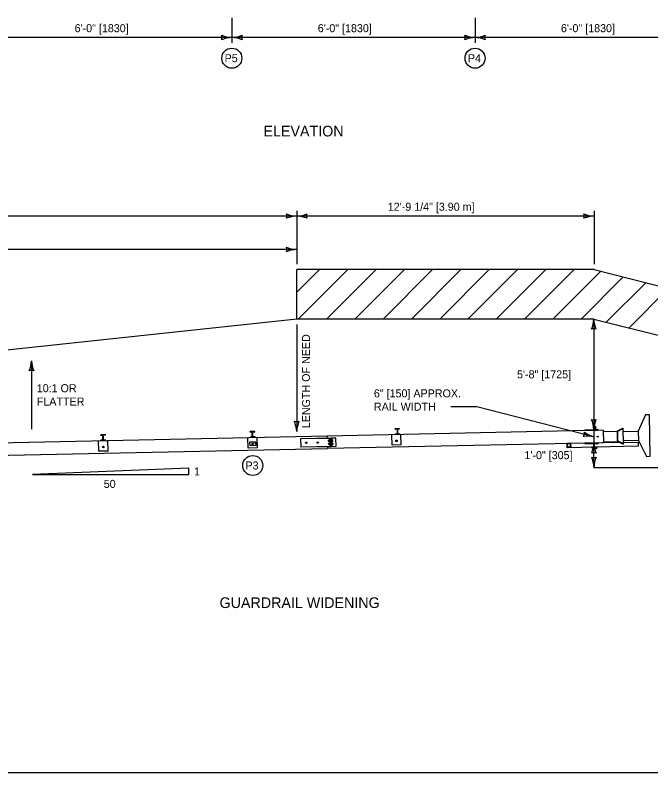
# Model space of a CAD drawing. Extents: x 49991.4 to 50021, y 49987.6 to 50011.4.
# Drawn here: x 50005.97 to 50010.73, y 49987.8 to 49993.48 of the extents above; entities that cross this region are included whole.
import ezdxf

# ---------------------------------------------------------------- set-up
doc = ezdxf.new("R2010")
doc.units = 0
for name, color, linetype in [('Level 1', 7, 'Continuous'), ('Level 2', 7, 'Continuous'), ('Level 3', 7, 'Continuous'), ('Level 4', 7, 'Continuous'), ('Level 63', 7, 'Continuous')]:
    doc.layers.add(name, color=color, linetype=linetype)

# ---------------------------------------------------------------- blocks, each defined once
blk = doc.blocks.new('HEX$NU')
at = {"layer": 'Level 63'}
for p, q in [((0, -0.32), (0, 0.32)), ((0.03, 0.43), (0.42, 0.43)), ((0.03, 0.22), (0.42, 0.22)), ((0.45, 0.32), (0.45, -0.32)), ((0.03, -0.22), (0.42, -0.22)), ((0.42, -0.43), (0.03, -0.43))]:
    blk.add_line(p, q, dxfattribs=at)
for centre, radius, start, end in [((0.21, 0.32), 0.21, 149.0201, 210.9799), ((0.8, 0), 0.796, 164.2217, 195.7782), ((0.24, 0.32), 0.21, 329.0201, 30.9799), ((-0.35, 0), 0.796, 344.2218, 15.7783), ((0.21, -0.32), 0.21, 149.0201, 210.9799), ((0.24, -0.32), 0.21, 329.0201, 30.9799)]:
    blk.add_arc(centre, radius, start, end, dxfattribs=at)

msp = doc.modelspace()

# ---------------------------------------------------------------- linework, layer by layer
at = {"layer": 'Level 1'}
for p, q in [((50008.0791, 49991.2004), (50008.0791, 49991.5719)), ((50008.0791, 49991.4009), (50008.2501, 49991.5719)), ((50010.3087, 49991.5719), (50008.0791, 49991.5719)), ((50008.0908, 49991.2004), (50008.4623, 49991.5719)), ((50008.3029, 49991.2004), (50008.6744, 49991.5719)), ((50008.5149, 49991.2004), (50008.8864, 49991.5719)), ((50008.7271, 49991.2004), (50009.0986, 49991.5719)), ((50008.9393, 49991.2004), (50009.3108, 49991.5719)), ((50009.1513, 49991.2004), (50009.5228, 49991.5719)), ((50009.3635, 49991.2004), (50009.735, 49991.5719)), ((50009.5757, 49991.2004), (50009.9472, 49991.5719)), ((50009.7877, 49991.2004), (50010.1592, 49991.5719)), ((50009.9999, 49991.2004), (50010.3586, 49991.5591)), ((50010.3087, 49991.5719), (50016.0878, 49990.0886)), ((50010.212, 49991.2004), (50010.5274, 49991.5157)), ((50010.4006, 49991.1767), (50010.6963, 49991.4724)), ((50010.5708, 49991.1348), (50010.8651, 49991.4291)), ((50008.0791, 49991.2004), (50001.0367, 49990.4473)), ((50010.3072, 49991.2004), (50008.0791, 49991.2004)), ((50010.3072, 49991.2004), (50014.7014, 49990.0886)), ((50010.6948, 49990.4815), (50010.6398, 49990.3599)), ((50010.7235, 49990.4821), (50010.6948, 49990.4815)), ((50010.73, 49990.1715), (50010.7235, 49990.4821)), ((50010.3783, 49990.3661), (50008.3088, 49990.3226)), ((50008.8174, 49990.3799), (50008.8509, 49990.3806)), ((50008.8175, 49990.3758), (50008.8174, 49990.3799)), ((50008.8175, 49990.3758), (50008.8294, 49990.3761)), ((50008.8331, 49990.3723), (50008.8338, 49990.3415)), ((50008.8356, 49990.3723), (50008.8362, 49990.3416)), ((50008.8391, 49990.3763), (50008.851, 49990.3765)), ((50008.851, 49990.3765), (50008.8509, 49990.3806)), ((50010.2413, 49990.3638), (50010.2413, 49990.3632)), ((50010.2478, 49990.3633), (50010.2478, 49990.364)), ((50010.3097, 49990.3792), (50010.3098, 49990.3736)), ((50010.3098, 49990.3736), (50010.3098, 49990.3717)), ((50010.3131, 49990.3799), (50010.3116, 49990.3798)), ((50010.3118, 49990.3711), (50010.3234, 49990.3714)), ((50010.3126, 49990.3928), (50010.3135, 49990.3938)), ((50010.3126, 49990.3928), (50010.3135, 49990.3938)), ((50010.3126, 49990.3928), (50010.3129, 49990.3798)), ((50010.3131, 49990.3799), (50010.3233, 49990.3801)), ((50010.3207, 49990.394), (50010.3135, 49990.3938)), ((50010.3207, 49990.394), (50010.3135, 49990.3938)), ((50010.3137, 49990.3717), (50010.3135, 49990.3793)), ((50010.3216, 49990.393), (50010.3207, 49990.394)), ((50010.3216, 49990.393), (50010.3207, 49990.394)), ((50010.3215, 49990.3719), (50010.3213, 49990.3794)), ((50010.3219, 49990.38), (50010.3216, 49990.393)), ((50010.3253, 49990.3744), (50010.3252, 49990.3795)), ((50010.3253, 49990.3744), (50010.3254, 49990.372)), ((50010.3281, 49990.3715), (50010.3328, 49990.3716)), ((50010.3329, 49990.3657), (50010.3282, 49990.3656)), ((50010.3329, 49990.3657), (50010.333, 49990.3651)), ((50010.3783, 49990.3661), (50010.3802, 49990.2729)), ((50010.4841, 49990.3619), (50010.5237, 49990.3829)), ((50010.5238, 49990.3776), (50010.4842, 49990.3567)), ((50010.5237, 49990.3829), (50010.5261, 49990.3777)), ((50010.5261, 49990.3777), (50010.5238, 49990.3776)), ((50010.5238, 49990.3776), (50010.5261, 49990.2675)), ((50010.5272, 49990.3226), (50010.5261, 49990.3777)), ((50010.5272, 49990.3226), (50010.5261, 49990.3741)), ((50008.3088, 49990.3226), (50004.9581, 49990.2521)), ((50006.6462, 49990.3342), (50006.61, 49990.3335)), ((50006.6102, 49990.3279), (50006.61, 49990.3335)), ((50006.6255, 49990.3282), (50006.6102, 49990.3279)), ((50006.6263, 49990.2928), (50006.6255, 49990.3282)), ((50006.6464, 49990.3286), (50006.6311, 49990.3283)), ((50006.6319, 49990.2929), (50006.6311, 49990.3283)), ((50006.6464, 49990.3286), (50006.6462, 49990.3342)), ((50007.766, 49990.3578), (50007.7298, 49990.357)), ((50007.7299, 49990.3514), (50007.7298, 49990.357)), ((50007.7452, 49990.3518), (50007.7299, 49990.3514)), ((50007.746, 49990.3164), (50007.7307, 49990.316)), ((50007.7308, 49990.3104), (50007.7307, 49990.316)), ((50007.746, 49990.3164), (50007.7452, 49990.3518)), ((50007.7661, 49990.3522), (50007.7508, 49990.3519)), ((50007.7516, 49990.3164), (50007.7508, 49990.3519)), ((50007.7669, 49990.3168), (50007.7516, 49990.3164)), ((50007.7661, 49990.3522), (50007.766, 49990.3578)), ((50007.7669, 49990.3112), (50007.7669, 49990.3168)), ((50008.3379, 49990.3076), (50008.1079, 49990.3028)), ((50008.2364, 49990.3055), (50008.3307, 49990.3075)), ((50008.3091, 49990.307), (50008.3088, 49990.3226)), ((50008.3088, 49990.3226), (50008.3091, 49990.307)), ((50008.332, 49990.2454), (50008.3307, 49990.3075)), ((50008.3738, 49990.3084), (50008.3379, 49990.3076)), ((50008.3392, 49990.2455), (50008.3379, 49990.3076)), ((50008.3428, 49990.2456), (50008.3415, 49990.3077)), ((50008.3751, 49990.2463), (50008.3738, 49990.3084)), ((50008.8585, 49990.3341), (50008.7938, 49990.3328)), ((50008.8302, 49990.3376), (50008.8183, 49990.3373)), ((50008.8184, 49990.3333), (50008.8183, 49990.3373)), ((50008.8519, 49990.334), (50008.8184, 49990.3333)), ((50008.8518, 49990.338), (50008.8399, 49990.3378)), ((50008.8519, 49990.334), (50008.8518, 49990.338)), ((50010.3784, 49990.3583), (50010.4842, 49990.3605)), ((50010.4861, 49990.3576), (50010.4841, 49990.3619)), ((50010.4842, 49990.3605), (50010.4848, 49990.3295)), ((50010.4842, 49990.3567), (50010.4857, 49990.2868)), ((50010.4857, 49990.2868), (50010.4842, 49990.3567)), ((50010.4842, 49990.3567), (50010.4865, 49990.3567)), ((50010.4858, 49990.2829), (50010.4851, 49990.314)), ((50010.4861, 49990.3576), (50010.4865, 49990.3567)), ((50010.5265, 49990.3576), (50010.6398, 49990.3599)), ((50010.5272, 49990.3226), (50010.5284, 49990.2675)), ((50010.5272, 49990.3226), (50010.5283, 49990.2712)), ((50010.6398, 49990.3599), (50010.6413, 49990.2901)), ((50006.6263, 49990.2928), (50006.611, 49990.2925)), ((50006.611, 49990.2869), (50006.611, 49990.2925)), ((50006.6472, 49990.2932), (50006.6319, 49990.2929)), ((50006.6472, 49990.2876), (50006.6472, 49990.2932)), ((50007.773, 49990.2784), (50007.7264, 49990.2774)), ((50007.7264, 49990.2774), (50007.727, 49990.2501)), ((50007.7735, 49990.2512), (50007.727, 49990.2501)), ((50007.7691, 49990.2784), (50007.7696, 49990.2511)), ((50007.773, 49990.2784), (50007.7735, 49990.2512)), ((50008.1079, 49990.3028), (50008.1092, 49990.2407)), ((50010.3802, 49990.2729), (50008.3108, 49990.2294)), ((50008.3193, 49990.2927), (50008.3184, 49990.2917)), ((50008.3186, 49990.2839), (50008.3184, 49990.2917)), ((50008.3195, 49990.283), (50008.3186, 49990.2839)), ((50008.3198, 49990.2694), (50008.3189, 49990.2684)), ((50008.3191, 49990.2606), (50008.3189, 49990.2684)), ((50008.32, 49990.2597), (50008.3191, 49990.2606)), ((50008.3193, 49990.2927), (50008.3231, 49990.2928)), ((50008.3193, 49990.2927), (50008.3195, 49990.283)), ((50008.3231, 49990.2918), (50008.3193, 49990.2917)), ((50008.3195, 49990.284), (50008.3233, 49990.284)), ((50008.3233, 49990.2831), (50008.3195, 49990.283)), ((50008.3198, 49990.2694), (50008.3236, 49990.2695)), ((50008.3198, 49990.2694), (50008.32, 49990.2597)), ((50008.3236, 49990.2685), (50008.3198, 49990.2684)), ((50008.32, 49990.2607), (50008.3238, 49990.2607)), ((50008.3238, 49990.2598), (50008.32, 49990.2597)), ((50008.3477, 49990.2926), (50008.3418, 49990.2925)), ((50008.3479, 49990.2842), (50008.342, 49990.2841)), ((50008.3482, 49990.2693), (50008.3423, 49990.2692)), ((50008.3484, 49990.2609), (50008.3424, 49990.2608)), ((50008.3483, 49990.2947), (50008.3485, 49990.2821)), ((50008.3488, 49990.2715), (50008.349, 49990.2589)), ((50010.4986, 49990.2754), (50010.1072, 49990.2672)), ((50010.1078, 49990.2361), (50010.1072, 49990.2672)), ((50010.1113, 49990.242), (50010.1109, 49990.2614)), ((50010.1306, 49990.2638), (50010.1126, 49990.2634)), ((50010.1328, 49990.2425), (50010.1324, 49990.2619)), ((50010.1366, 49990.2367), (50010.1359, 49990.2678)), ((50010.2498, 49990.2702), (50010.2498, 49990.2695)), ((50010.3284, 49990.2718), (50010.3284, 49990.2712)), ((50010.3349, 49990.272), (50010.3349, 49990.2713)), ((50010.3801, 49990.2807), (50010.4858, 49990.2829)), ((50010.5261, 49990.2675), (50010.4857, 49990.2868)), ((50010.4876, 49990.2859), (50010.4858, 49990.2815)), ((50010.4858, 49990.2815), (50010.5262, 49990.2622)), ((50010.5284, 49990.2675), (50010.5261, 49990.2675)), ((50010.5262, 49990.2622), (50010.5284, 49990.2675)), ((50010.6413, 49990.2901), (50010.528, 49990.2877)), ((50010.5282, 49990.276), (50010.6389, 49990.2784)), ((50010.6389, 49990.2784), (50010.6396, 49990.2473)), ((50010.6413, 49990.2901), (50010.7013, 49990.1709)), ((50008.3392, 49990.2455), (50008.1092, 49990.2407)), ((50008.2377, 49990.2434), (50008.332, 49990.2454)), ((50008.3104, 49990.2449), (50008.3108, 49990.2294)), ((50008.3392, 49990.2455), (50008.3751, 49990.2463)), ((50010.6396, 49990.2473), (50010.1078, 49990.2361)), ((50010.1311, 49990.2405), (50010.1131, 49990.2401)), ((50010.2899, 49990.2371), (50010.2946, 49990.2372)), ((50010.2899, 49990.2371), (50010.2946, 49990.2372)), ((50010.2907, 49990.2374), (50010.2906, 49990.24)), ((50010.2907, 49990.2374), (50010.2906, 49990.24)), ((50010.2938, 49990.2375), (50010.2938, 49990.24)), ((50010.2938, 49990.2375), (50010.2938, 49990.24)), ((50010.3146, 49990.232), (50010.3286, 49990.2323)), ((50010.3146, 49990.232), (50010.3286, 49990.2323)), ((50010.3169, 49990.2328), (50010.3168, 49990.2405)), ((50010.3169, 49990.2328), (50010.3168, 49990.2405)), ((50010.3263, 49990.233), (50010.3261, 49990.2407)), ((50010.3263, 49990.233), (50010.3261, 49990.2407)), ((50010.7013, 49990.1709), (50010.73, 49990.1715))]:
    msp.add_line(p, q, dxfattribs=at)
for points in [[(49999.3835, 49998.9992), (50016.7501, 49998.9992), (50016.7501, 49987.7988), (49999.3835, 49987.7988)], [(50010.336, 49990.3228), (50010.3394, 49990.3208), (50010.3395, 49990.3166), (50010.3362, 49990.3144), (50010.3328, 49990.3164), (50010.3327, 49990.3206)]]:
    msp.add_lwpolyline(points, close=True, dxfattribs=at)
for points in [[(50010.3329, 49990.3657), (50010.2413, 49990.3638), (50010.2411, 49990.3696), (50010.3328, 49990.3716)], [(50008.348, 49990.28), (50008.342, 49990.2799), (50008.3417, 49990.2967), (50008.3476, 49990.2968)], [(50008.3484, 49990.2567), (50008.3425, 49990.2566), (50008.3422, 49990.2734), (50008.3481, 49990.2735)], [(50010.3351, 49990.2655), (50010.2434, 49990.2636), (50010.2432, 49990.2694), (50010.3349, 49990.2713)], [(50004.9601, 49990.1589), (50008.3108, 49990.2294)], [(50010.2954, 49990.2375), (50010.2953, 49990.2401), (50010.2891, 49990.2399), (50010.2891, 49990.2374)], [(50010.2954, 49990.2375), (50010.2953, 49990.2401), (50010.2891, 49990.2399), (50010.2891, 49990.2374)], [(50010.3309, 49990.2331), (50010.3308, 49990.2408), (50010.3121, 49990.2404), (50010.3123, 49990.2327)], [(50010.3309, 49990.2331), (50010.3308, 49990.2408), (50010.3121, 49990.2404), (50010.3123, 49990.2327)], [(50010.308, 49990.0886), (50016.0878, 49990.0886)]]:
    msp.add_lwpolyline(points, dxfattribs=at)
for centre in [(50007.7499, 49990.2642), (50008.8275, 49990.2874), (50006.6302, 49990.2407)]:
    msp.add_circle(centre, 0.00582, dxfattribs=at)
for centre, major_axis, start_param, end_param in [((50008.8295, 49990.3722), (0.00008, -0.00388), 1.570796, 3.141593), ((50008.8391, 49990.3724), (0.00008, -0.00388), 3.141593, 4.712389), ((50010.3117, 49990.3757), (0.00009, -0.00408), 2.720968, 3.682294), ((50010.3117, 49990.3752), (0.00009, -0.00408), 5.742484, 6.823887), ((50010.3117, 49990.3757), (0.00009, -0.00408), 2.600891, 2.720968), ((50010.3177, 49990.3645), (0.0003, -0.0155), 2.86621, 3.416974), ((50010.3173, 49990.3867), (0.0003, -0.0155), 6.007804, 6.558569), ((50010.3233, 49990.376), (0.00009, -0.00408), 2.967765, 3.682294), ((50010.3234, 49990.3755), (0.00009, -0.00408), 5.742484, 6.823887), ((50010.3233, 49990.376), (0.00009, -0.00408), 2.600891, 2.967765), ((50010.3331, 49990.3599), (0.0002, -0.0116), 2.033833, 3.141593), ((50010.3331, 49990.3599), (0.00012, -0.00582), 2.675505, 3.141593), ((50008.8302, 49990.3415), (0.00008, -0.00388), 0, 1.570796), ((50008.8398, 49990.3417), (0.00008, -0.00388), 4.712389, 6.283185), ((50010.3361, 49990.3186), (0.00005, -0.00216), 4.763342, 5.105427), ((50010.3361, 49990.3186), (0.00005, -0.00216), 4.763342, 5.105427), ((50010.3361, 49990.3186), (0.00005, -0.00216), 3.992248, 4.383081), ((50010.3361, 49990.3186), (0.00005, -0.00216), 3.992248, 4.383081), ((50010.3361, 49990.3186), (0.00005, -0.00216), 5.354777, 5.790079), ((50010.3361, 49990.3186), (0.00005, -0.00216), 5.354777, 5.790079), ((50010.3361, 49990.3186), (0.00005, -0.00216), 3.449353, 3.624539), ((50010.3361, 49990.3186), (0.00005, -0.00216), 3.449353, 3.624539), ((50010.3361, 49990.3186), (0.00005, -0.00216), 2.884373, 3.117684), ((50010.3361, 49990.3186), (0.00005, -0.00216), 2.884373, 3.117684), ((50010.3361, 49990.3186), (0.00005, -0.00216), 2.884373, 3.117684), ((50010.3361, 49990.3186), (0.00005, -0.00216), 2.884373, 3.117684), ((50010.3361, 49990.3186), (0.00005, -0.00216), 6.236416, 6.677165), ((50010.3361, 49990.3186), (0.00005, -0.00216), 2.117521, 2.495297), ((50010.3361, 49990.3186), (0.00005, -0.00216), 2.117521, 2.495297), ((50010.3361, 49990.3186), (0.00005, -0.00216), 2.117521, 2.495297), ((50010.3361, 49990.3186), (0.00005, -0.00216), 2.117521, 2.495297), ((50010.3361, 49990.3186), (0.00005, -0.00216), 0.757801, 1.088721), ((50010.3361, 49990.3186), (0.00005, -0.00216), 0.757801, 1.088721), ((50010.3361, 49990.3186), (0.00005, -0.00216), 0.757801, 1.088721), ((50010.3361, 49990.3186), (0.00005, -0.00216), 0.757801, 1.088721), ((50010.3361, 49990.3186), (0.00005, -0.00216), 1.432819, 1.796691), ((50010.3361, 49990.3186), (0.00005, -0.00216), 1.432819, 1.796691), ((50010.3361, 49990.3186), (0.00005, -0.00216), 1.432819, 1.796691), ((50010.3361, 49990.3186), (0.00005, -0.00216), 1.432819, 1.796691), ((50008.3449, 49990.2947), (0.00008, -0.00359), 0.945365, 2.196228), ((50008.3361, 49990.2882), (0.0003, -0.0133), 1.250246, 1.891347), ((50008.3452, 49990.2821), (0.00008, -0.00359), 0.945366, 2.196226), ((50008.3454, 49990.2714), (0.00008, -0.00359), 0.945365, 2.196228), ((50008.3365, 49990.2649), (0.0003, -0.0133), 1.250246, 1.891347), ((50008.3457, 49990.2588), (0.00008, -0.00359), 0.945366, 2.196226), ((50010.1127, 49990.2615), (0.00004, -0.00194), 3.141593, 4.712389), ((50010.1306, 49990.2618), (0.00004, -0.00194), 1.570796, 3.141593), ((50010.3348, 49990.2772), (0.00012, -0.00582), 0, 0.466088), ((50010.3348, 49990.2772), (0.0002, -0.0116), 0, 1.10776), ((50010.1131, 49990.2421), (0.00004, -0.00194), 4.712389, 6.283185), ((50010.131, 49990.2424), (0.00004, -0.00194), 0, 1.570796), ((50010.2899, 49990.2386), (0.00003, -0.00144), 5.657754, 6.908617), ((50010.2899, 49990.2386), (0.00003, -0.00144), 5.657754, 6.908617), ((50010.2922, 49990.2425), (0.00011, -0.00533), 5.962635, 6.603736), ((50010.2922, 49990.2425), (0.00011, -0.00533), 5.962635, 6.603736), ((50010.2946, 49990.2387), (0.00003, -0.00144), 5.657755, 6.908615), ((50010.2946, 49990.2387), (0.00003, -0.00144), 5.657755, 6.908615), ((50010.3145, 49990.2363), (0.00009, -0.00431), 5.657754, 6.908617), ((50010.3145, 49990.2363), (0.00009, -0.00431), 5.657754, 6.908617), ((50010.3213, 49990.2481), (0.0003, -0.016), 5.962635, 6.603736), ((50010.3213, 49990.2481), (0.0003, -0.016), 5.962635, 6.603736), ((50010.3285, 49990.2366), (0.00009, -0.00431), 5.657755, 6.908615), ((50010.3285, 49990.2366), (0.00009, -0.00431), 5.657755, 6.908615)]:
    msp.add_ellipse(centre, major_axis=major_axis, ratio=0.925528, start_param=start_param, end_param=end_param, dxfattribs=at)
for centre, major_axis in [((50010.3361, 49990.3186), (0.00005, -0.00243)), ((50010.3361, 49990.3186), (0.00005, -0.00243)), ((50008.1511, 49990.2726), (0.00012, -0.00566)), ((50008.2373, 49990.2745), (0.00012, -0.00566))]:
    msp.add_ellipse(centre, major_axis=major_axis, ratio=0.925528, dxfattribs=at)
at = {"layer": 'Level 2'}
for p, q in [((50007.2698, 49990.0814), (50006.0979, 49990.0346)), ((50007.2698, 49990.0346), (50007.2698, 49990.0814)), ((50006.0979, 49990.0346), (50007.2698, 49990.0346))]:
    msp.add_line(p, q, dxfattribs=at)
for centre in [(50007.5932, 49993.1553), (50009.4164, 49993.1553), (50007.7499, 49990.1026)]:
    msp.add_circle(centre, 0.075, dxfattribs=at)
at = {"layer": 'Level 3'}
for p, q in [((50007.5932, 49993.458), (50007.5932, 49993.2703)), ((50009.4164, 49993.458), (50009.4164, 49993.2703)), ((50007.5932, 49993.3103), (50005.7702, 49993.3103)), ((50009.4164, 49993.3103), (50007.5932, 49993.3103)), ((50011.2396, 49993.3103), (50009.4164, 49993.3103)), ((50008.0791, 49992.0119), (50008.0791, 49991.6119)), ((50010.3086, 49992.0119), (50010.3086, 49991.6119)), ((50008.0791, 49991.9719), (50001.0367, 49991.9719)), ((50010.3086, 49991.9719), (50008.0791, 49991.9719)), ((50008.0791, 49991.7219), (50001.5952, 49991.7219)), ((50008.0791, 49991.1604), (50008.0791, 49990.3577)), ((50010.3063, 49991.2004), (50010.3063, 49990.371)), ((50006.0906, 49990.8877), (50006.0906, 49990.3759)), ((50009.4309, 49990.5432), (50009.2355, 49990.5432)), ((50010.3072, 49990.3176), (50009.4309, 49990.5432)), ((50010.3063, 49990.3646), (50010.308, 49990.2714)), ((50010.308, 49990.0886), (50010.308, 49990.2714))]:
    msp.add_line(p, q, dxfattribs=at)
for centre, radius, start, end in [((50007.6024, 49993.5324), 0.2223, 247.456, 267.6395), ((50007.465, 49993.3103), 0.0548, 342.1388, 17.8612), ((50007.5817, 49993.543), 0.233, 272.8273, 292.0772), ((50007.7214, 49993.3103), 0.0548, 162.1388, 197.8612), ((50009.4256, 49993.5324), 0.2223, 247.456, 267.6395), ((50009.2882, 49993.3103), 0.0548, 342.1388, 17.8612), ((50009.4049, 49993.543), 0.233, 272.8273, 292.0772), ((50009.5446, 49993.3103), 0.0548, 162.1388, 197.8612), ((50007.6047, 49993.0776), 0.233, 92.8273, 112.0772), ((50007.584, 49993.0882), 0.2223, 67.456, 87.6395), ((50009.4279, 49993.0776), 0.233, 92.8273, 112.0772), ((50009.4072, 49993.0882), 0.2223, 67.456, 87.6395), ((50008.0883, 49992.194), 0.2223, 247.456, 267.6395), ((50007.9509, 49991.9719), 0.0548, 342.1388, 17.8612), ((50008.0906, 49991.7392), 0.233, 92.8273, 112.0772), ((50008.0676, 49992.2046), 0.233, 272.8273, 292.0772), ((50008.0699, 49991.7498), 0.2223, 67.456, 87.6395), ((50008.2073, 49991.9719), 0.0548, 162.1388, 197.8612), ((50010.3178, 49992.194), 0.2223, 247.456, 267.6395), ((50010.1804, 49991.9719), 0.0548, 342.1388, 17.8612), ((50010.3201, 49991.7392), 0.233, 92.8273, 112.0772), ((50008.0883, 49991.944), 0.2223, 247.456, 267.6395), ((50007.9509, 49991.7219), 0.0548, 342.1388, 17.8612), ((50008.0906, 49991.4892), 0.233, 92.8273, 112.0772), ((50010.0842, 49991.2095), 0.2223, 337.456, 357.6395), ((50010.539, 49991.2119), 0.233, 182.8273, 202.0772), ((50010.3063, 49991.0722), 0.0548, 72.1388, 107.8612), ((50005.8685, 49990.8969), 0.2223, 337.456, 357.6395), ((50006.3233, 49990.8992), 0.233, 182.8273, 202.0772), ((50006.0906, 49990.7595), 0.0548, 72.1388, 107.8612), ((50008.0791, 49990.4859), 0.0548, 252.1388, 287.8612), ((50007.8464, 49990.3462), 0.233, 2.8273, 22.0772), ((50008.3012, 49990.3486), 0.2223, 157.456, 177.6395), ((50010.3063, 49990.4992), 0.0548, 252.1388, 287.8612), ((50010.0736, 49990.3595), 0.233, 2.8273, 22.0772), ((50010.5284, 49990.3619), 0.2223, 157.456, 177.6395), ((50010.1826, 49990.3479), 0.0548, 328.4642, 4.1866), ((50010.2633, 49990.0887), 0.233, 79.1527, 98.4026), ((50010.3686, 49990.5312), 0.2223, 233.7814, 253.9649), ((50010.0859, 49990.2806), 0.2223, 337.456, 357.6395), ((50010.5407, 49990.2829), 0.233, 182.8273, 202.0772), ((50010.308, 49990.1432), 0.0548, 72.1388, 107.8612), ((50010.308, 49990.2168), 0.0548, 252.1388, 287.8612), ((50010.0753, 49990.0771), 0.233, 2.8273, 22.0772), ((50010.5301, 49990.0794), 0.2223, 157.456, 177.6395)]:
    msp.add_arc(centre, radius, start, end, dxfattribs=at)
at = {"layer": 'Level 4'}
for p, q in [((50007.7155, 49990.2324), (50007.7139, 49990.3101)), ((50007.7854, 49990.2338), (50007.7837, 49990.3115)), ((50008.7955, 49990.2551), (50008.7938, 49990.3328)), ((50008.8585, 49990.3341), (50008.8601, 49990.2565)), ((50006.5958, 49990.2088), (50006.5941, 49990.2866)), ((50006.6656, 49990.2104), (50006.664, 49990.288)), ((50008.8601, 49990.2565), (50008.7955, 49990.2551)), ((50006.6656, 49990.2104), (50006.5958, 49990.2088)), ((50007.7854, 49990.2338), (50007.7155, 49990.2324))]:
    msp.add_line(p, q, dxfattribs=at)

# ---------------------------------------------------------------- block references
at = {"layer": 'Level 1', "xscale": 0.017968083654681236, "yscale": -0.019413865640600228, "rotation": 1.2045520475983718}
for p in [(50008.3232, 49990.2886), (50008.3238, 49990.2652)]:
    msp.add_blockref('HEX$NU', p, dxfattribs=at)

# ---------------------------------------------------------------- texts
at = {"layer": 'Level 2'}
for s, height, p in [('6\'-0" [1830]', 0.06, (50006.4142, 49993.3503)), ('6\'-0" [1830]', 0.06, (50008.2373, 49993.3503)), ('6\'-0" [1830]', 0.06, (50010.0605, 49993.3503)), ('P5', 0.06, (50007.5389, 49993.1253)), ('P4', 0.06, (50009.363, 49993.1253)), ('ELEVATION', 0.08, (50007.8304, 49992.5689)), ('12\'-9 1/4" [3.90 m]', 0.06, (50008.7622, 49992.0119)), ('5\'-8" [1725]', 0.06, (50009.7312, 49990.7557)), ('10:1 OR', 0.06, (50006.1306, 49990.6518)), ('6" [150] APPROX. ', 0.06, (50008.6582, 49990.6132)), ('FLATTER', 0.06, (50006.1306, 49990.5518)), ('RAIL WIDTH', 0.06, (50008.6582, 49990.5132)), ('1\'-0" [305]', 0.06, (50009.7868, 49990.15)), ('1', 0.06, (50007.3098, 49990.028)), ('P3', 0.06, (50007.6953, 49990.0726)), ('50', 0.06, (50006.6327, 49989.9346)), ('GUARDRAIL WIDENING', 0.08, (50007.5011, 49989.0342))]:
    msp.add_text(s, height=height, dxfattribs=at).set_placement(p)
msp.add_text('LENGTH OF NEED', height=0.06, rotation=90, dxfattribs=at).set_placement((50008.1791, 49990.382))

doc.saveas('drawing.dxf')
